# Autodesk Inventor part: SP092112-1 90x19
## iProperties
Created: 2012-09
Part Number: SP092112-1 90x19
Material: Aluminum-6061
Description: PROFILE 90X19
Document SubType Name: Modeling
Designer: Administrator
Stock Number: 20.0995 PROFILE 90X19
Density: 2.71 g/cm^3
Mass: 2435.55 g
Surface Area: 5914.91 cm^2
Volume: 898.727 cm^3
Author: Administrator
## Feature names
1. Extrusion1
